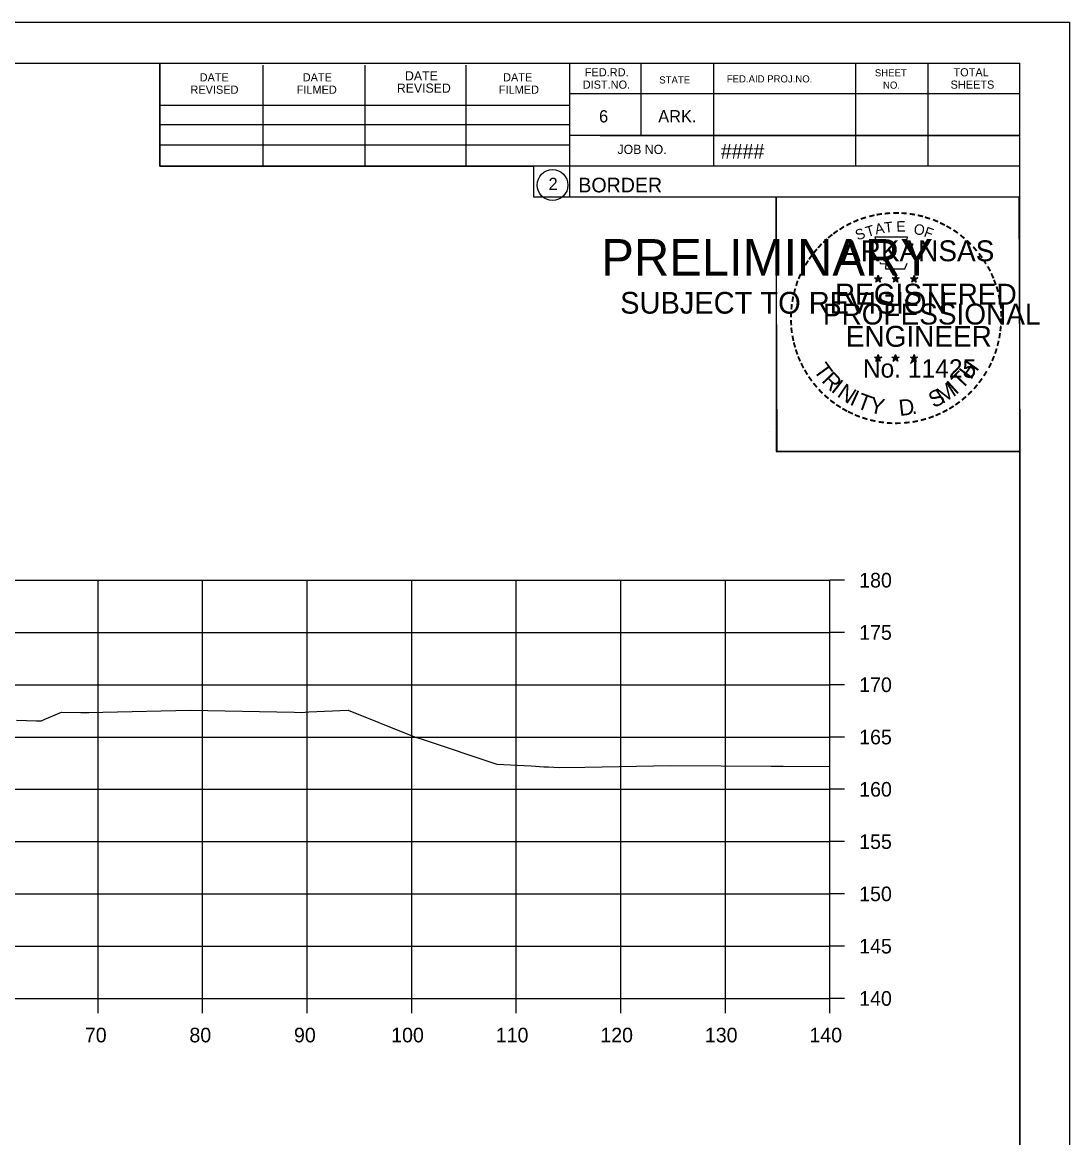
# Model space of a CAD drawing. Extents: x 1368503 to 1373085, y 379840 to 381833.
# Drawn here: x 1372984.8 to 1373085, y 380495 to 380601.6 of the extents above; entities that cross this region are included whole.
import ezdxf

# ---------------------------------------------------------------- set-up
doc = ezdxf.new("R2010")
doc.units = 0
for name, color, linetype in [('S_BRIDGE', 7, 'Continuous'), ('S_EDGE_PAVEMENT', 7, 'Continuous'), ('S_LANDSCAPING', 7, 'Continuous'), ('S_MISC_BOUNDARY', 7, 'Continuous'), ('S_MISC_BOUNDARY_ANNOT', 7, 'Continuous'), ('S_PHOTO_CENTERS', 7, 'Continuous'), ('S_PHOTO_NOTES', 7, 'Continuous'), ('S_TRAILS', 7, 'Continuous')]:
    doc.layers.add(name, color=color, linetype=linetype)

msp = doc.modelspace()

# ---------------------------------------------------------------- linework, layer by layer
at = {"layer": 'S_BRIDGE'}
for p, q in [((1372764.08, 380597.75), (1373080.26, 380597.75)), ((1372998, 380587.87), (1372998, 380597.75)), ((1373007.86, 380587.87), (1373007.86, 380597.55)), ((1373017.62, 380587.87), (1373017.62, 380597.55)), ((1373027.3, 380587.87), (1373027.3, 380597.55)), ((1373037.16, 380597.75), (1373037.16, 380584.95)), ((1373044, 380597.75), (1373044, 380590.81)), ((1373050.94, 380597.75), (1373050.94, 380587.87)), ((1373064.52, 380597.75), (1373064.52, 380587.87)), ((1373071.46, 380597.75), (1373071.46, 380587.87)), ((1373080.26, 380392.29), (1373080.26, 380597.75)), ((1373080.26, 380594.81), (1373037.16, 380594.81)), ((1373080.26, 380594.83), (1373080.26, 380594.83)), ((1372998, 380593.73), (1373037.16, 380593.73)), ((1372998, 380591.87), (1373037.16, 380591.87)), ((1373080.26, 380590.81), (1373037.16, 380590.81)), ((1373040.12, 380590.81), (1373080.26, 380590.81)), ((1372998, 380587.87), (1372998, 380589.93)), ((1372998, 380589.93), (1373037.16, 380589.93)), ((1373080.26, 380587.87), (1372998, 380587.87)), ((1373037.16, 380584.95), (1373080.26, 380584.95))]:
    msp.add_line(p, q, dxfattribs=at)
msp.add_circle((1373035.55, 380586.08), 1.47, dxfattribs=at)
at = {"layer": 'S_EDGE_PAVEMENT'}
for p, q in [((1373062.08, 380508.29), (1373062.08, 380548.29)), ((1373063.48, 380548.29), (1373062.08, 380548.29)), ((1373063.48, 380543.29), (1373062.08, 380543.29)), ((1373063.48, 380538.29), (1373062.08, 380538.29)), ((1373063.48, 380533.29), (1373062.08, 380533.29)), ((1373063.48, 380528.29), (1373062.08, 380528.29)), ((1373063.48, 380523.29), (1373062.08, 380523.29)), ((1373063.48, 380518.29), (1373062.08, 380518.29)), ((1373063.48, 380513.29), (1373062.08, 380513.29)), ((1372782.08, 380508.29), (1373062.08, 380508.29)), ((1372992.08, 380506.89), (1372992.08, 380508.29)), ((1373002.08, 380506.89), (1373002.08, 380508.29)), ((1373012.08, 380506.89), (1373012.08, 380508.29)), ((1373022.08, 380506.89), (1373022.08, 380508.29)), ((1373032.08, 380506.89), (1373032.08, 380508.29)), ((1373042.08, 380506.89), (1373042.08, 380508.29)), ((1373052.08, 380506.89), (1373052.08, 380508.29)), ((1373062.08, 380506.89), (1373062.08, 380508.29)), ((1373063.48, 380508.29), (1373062.08, 380508.29))]:
    msp.add_line(p, q, dxfattribs=at)
at = {"layer": 'S_LANDSCAPING'}
for p, q in [((1373066.7, 380577.46), (1373066.65, 380577.2)), ((1373066.7, 380577.09), (1373066.7, 380577.46)), ((1373066.7, 380577.46), (1373066.74, 380577.21)), ((1373068.37, 380577.46), (1373068.32, 380577.2)), ((1373068.37, 380577.09), (1373068.37, 380577.46)), ((1373068.37, 380577.46), (1373068.41, 380577.21)), ((1373070.13, 380577.44), (1373070.09, 380577.19)), ((1373070.13, 380577.08), (1373070.13, 380577.44)), ((1373070.13, 380577.44), (1373070.18, 380577.19)), ((1373066.35, 380577.2), (1373066.7, 380577.09)), ((1373066.35, 380577.2), (1373066.6, 380577.16)), ((1373066.35, 380577.2), (1373066.58, 380577.08)), ((1373066.48, 380576.79), (1373066.7, 380577.09)), ((1373066.48, 380576.79), (1373066.61, 380577.04)), ((1373066.48, 380576.79), (1373066.69, 380577.01)), ((1373066.91, 380576.79), (1373066.69, 380577.01)), ((1373067.04, 380577.2), (1373066.7, 380577.09)), ((1373066.91, 380576.79), (1373066.7, 380577.09)), ((1373067.04, 380577.2), (1373066.76, 380577.15)), ((1373066.91, 380576.79), (1373066.77, 380577.09)), ((1373067.04, 380577.2), (1373066.84, 380577.1)), ((1373068.02, 380577.2), (1373068.37, 380577.09)), ((1373068.02, 380577.2), (1373068.27, 380577.16)), ((1373068.02, 380577.2), (1373068.25, 380577.08)), ((1373068.15, 380576.79), (1373068.37, 380577.09)), ((1373068.15, 380576.79), (1373068.28, 380577.04)), ((1373068.15, 380576.79), (1373068.36, 380577.01)), ((1373068.58, 380576.79), (1373068.36, 380577.01)), ((1373068.71, 380577.2), (1373068.37, 380577.09)), ((1373068.58, 380576.79), (1373068.37, 380577.09)), ((1373068.71, 380577.2), (1373068.43, 380577.15)), ((1373068.58, 380576.79), (1373068.44, 380577.09)), ((1373068.71, 380577.2), (1373068.51, 380577.1)), ((1373069.78, 380577.19), (1373070.13, 380577.08)), ((1373069.78, 380577.19), (1373070.03, 380577.15)), ((1373069.78, 380577.19), (1373070.02, 380577.07)), ((1373069.91, 380576.78), (1373070.13, 380577.08)), ((1373069.91, 380576.78), (1373070.04, 380577.03)), ((1373069.91, 380576.78), (1373070.13, 380577)), ((1373070.48, 380577.19), (1373070.13, 380577.08)), ((1373070.34, 380576.78), (1373070.13, 380577.08)), ((1373070.34, 380576.78), (1373070.13, 380577)), ((1373070.48, 380577.19), (1373070.19, 380577.14)), ((1373070.34, 380576.78), (1373070.21, 380577.07)), ((1373070.48, 380577.19), (1373070.27, 380577.09)), ((1373066.69, 380569.88), (1373066.65, 380569.63)), ((1373066.69, 380569.52), (1373066.69, 380569.88)), ((1373066.69, 380569.88), (1373066.74, 380569.63)), ((1373068.36, 380569.88), (1373068.32, 380569.63)), ((1373068.36, 380569.52), (1373068.36, 380569.88)), ((1373068.36, 380569.88), (1373068.41, 380569.63)), ((1373070.13, 380569.87), (1373070.09, 380569.62)), ((1373070.13, 380569.51), (1373070.13, 380569.87)), ((1373070.13, 380569.87), (1373070.18, 380569.62)), ((1373066.34, 380569.63), (1373066.69, 380569.52)), ((1373066.34, 380569.63), (1373066.6, 380569.58)), ((1373066.34, 380569.63), (1373066.58, 380569.51)), ((1373066.48, 380569.22), (1373066.69, 380569.52)), ((1373066.48, 380569.22), (1373066.6, 380569.47)), ((1373066.48, 380569.22), (1373066.69, 380569.44)), ((1373067.04, 380569.63), (1373066.69, 380569.52)), ((1373066.9, 380569.22), (1373066.69, 380569.52)), ((1373066.9, 380569.22), (1373066.69, 380569.44)), ((1373067.04, 380569.63), (1373066.75, 380569.58)), ((1373066.9, 380569.22), (1373066.77, 380569.51)), ((1373067.04, 380569.63), (1373066.83, 380569.53)), ((1373068.01, 380569.63), (1373068.36, 380569.52)), ((1373068.01, 380569.63), (1373068.26, 380569.58)), ((1373068.01, 380569.63), (1373068.25, 380569.51)), ((1373068.14, 380569.22), (1373068.36, 380569.52)), ((1373068.14, 380569.22), (1373068.27, 380569.47)), ((1373068.14, 380569.22), (1373068.36, 380569.44)), ((1373068.71, 380569.63), (1373068.36, 380569.52)), ((1373068.57, 380569.22), (1373068.36, 380569.52)), ((1373068.57, 380569.22), (1373068.36, 380569.44)), ((1373068.71, 380569.63), (1373068.42, 380569.58)), ((1373068.57, 380569.22), (1373068.44, 380569.51)), ((1373068.71, 380569.63), (1373068.5, 380569.53)), ((1373069.78, 380569.62), (1373070.13, 380569.51)), ((1373069.78, 380569.62), (1373070.03, 380569.57)), ((1373069.78, 380569.62), (1373070.02, 380569.5)), ((1373069.91, 380569.21), (1373070.13, 380569.51)), ((1373069.91, 380569.21), (1373070.04, 380569.46)), ((1373069.91, 380569.21), (1373070.13, 380569.43)), ((1373070.47, 380569.62), (1373070.13, 380569.51)), ((1373070.34, 380569.21), (1373070.13, 380569.51)), ((1373070.34, 380569.21), (1373070.13, 380569.43)), ((1373070.47, 380569.62), (1373070.19, 380569.57)), ((1373070.34, 380569.21), (1373070.2, 380569.5)), ((1373070.47, 380569.62), (1373070.27, 380569.52))]:
    msp.add_line(p, q, dxfattribs=at)
for points in [[(1373066.39, 380581.08), (1373066.66, 380580.25)], [(1373069.9, 380580.16), (1373070.04, 380580.44), (1373069.36, 380580.42), (1373069.5, 380581.08), (1373066.39, 380581.08)], [(1373066.88, 380578.66), (1373066.88, 380578.57), (1373067.44, 380578.55), (1373067.39, 380578.08), (1373069.26, 380578.08), (1373069.46, 380578.61)], [(1373066.7, 380577.46), (1373066.91, 380576.79), (1373066.35, 380577.2), (1373067.04, 380577.2), (1373066.48, 380576.79), (1373066.7, 380577.46)], [(1373068.37, 380577.46), (1373068.58, 380576.79), (1373068.02, 380577.2), (1373068.71, 380577.2), (1373068.15, 380576.79), (1373068.37, 380577.46)], [(1373070.13, 380577.44), (1373070.34, 380576.78), (1373069.78, 380577.19), (1373070.48, 380577.19), (1373069.91, 380576.78), (1373070.13, 380577.44)], [(1373066.69, 380569.88), (1373066.9, 380569.22), (1373066.34, 380569.63), (1373067.04, 380569.63), (1373066.48, 380569.22), (1373066.69, 380569.88)], [(1373068.36, 380569.88), (1373068.57, 380569.22), (1373068.01, 380569.63), (1373068.71, 380569.63), (1373068.14, 380569.22), (1373068.36, 380569.88)], [(1373070.13, 380569.87), (1373070.34, 380569.21), (1373069.78, 380569.62), (1373070.47, 380569.62), (1373069.91, 380569.21), (1373070.13, 380569.87)]]:
    msp.add_lwpolyline(points, dxfattribs=at)
for centre, radius in [((1373066.69, 380577.09), 0.172), ((1373066.69, 380577.09), 0.145), ((1373068.36, 380577.09), 0.172), ((1373068.36, 380577.09), 0.145), ((1373070.13, 380577.08), 0.172), ((1373070.13, 380577.08), 0.145), ((1373066.69, 380577.09), 0.116), ((1373066.69, 380577.09), 0.0991), ((1373066.69, 380577.09), 0.0747), ((1373066.69, 380577.09), 0.0495), ((1373066.69, 380577.09), 0.0296), ((1373068.36, 380577.09), 0.116), ((1373068.36, 380577.09), 0.0991), ((1373068.36, 380577.09), 0.0747), ((1373068.36, 380577.09), 0.0495), ((1373068.36, 380577.09), 0.0296), ((1373070.13, 380577.08), 0.116), ((1373070.13, 380577.08), 0.0991), ((1373070.13, 380577.08), 0.0747), ((1373070.13, 380577.08), 0.0495), ((1373070.13, 380577.08), 0.0296), ((1373066.69, 380569.52), 0.172), ((1373066.69, 380569.52), 0.145), ((1373066.69, 380569.52), 0.116), ((1373066.69, 380569.52), 0.0991), ((1373066.69, 380569.52), 0.0747), ((1373066.69, 380569.52), 0.0495), ((1373066.69, 380569.52), 0.0296), ((1373068.36, 380569.52), 0.172), ((1373068.36, 380569.52), 0.145), ((1373068.36, 380569.52), 0.116), ((1373068.36, 380569.52), 0.0991), ((1373068.36, 380569.52), 0.0747), ((1373068.36, 380569.52), 0.0495), ((1373068.36, 380569.52), 0.0296), ((1373070.13, 380569.51), 0.172), ((1373070.13, 380569.51), 0.145), ((1373070.13, 380569.51), 0.116), ((1373070.13, 380569.51), 0.0991), ((1373070.13, 380569.51), 0.0747), ((1373070.13, 380569.51), 0.0495), ((1373070.13, 380569.51), 0.0296)]:
    msp.add_circle(centre, radius, dxfattribs=at)
at = {"layer": 'S_MISC_BOUNDARY'}
msp.add_lwpolyline([(1372984.28, 380534.9), (1372986.19, 380534.85), (1372986.67, 380534.84), (1372986.92, 380534.96), (1372988.59, 380535.67), (1372990.45, 380535.65), (1372991.2, 380535.65), (1372992.53, 380535.67), (1373000.92, 380535.85), (1373010.85, 380535.66), (1373011.53, 380535.65), (1373012.24, 380535.69), (1373015.99, 380535.87), (1373022.02, 380533.44), (1373022.44, 380533.28), (1373023.07, 380533.08), (1373030.21, 380530.71), (1373033.5, 380530.52), (1373034.72, 380530.45), (1373035.17, 380530.43), (1373036.17, 380530.39), (1373038.64, 380530.41), (1373046.87, 380530.56), (1373056.46, 380530.49), (1373056.89, 380530.49), (1373057.62, 380530.49), (1373062.08, 380530.48)], dxfattribs=at)
at = {"layer": 'S_PHOTO_CENTERS'}
for p, q in [((1372782.08, 380548.29), (1373062.08, 380548.29)), ((1372992.08, 380508.29), (1372992.08, 380548.29)), ((1373002.08, 380508.29), (1373002.08, 380548.29)), ((1373012.08, 380508.29), (1373012.08, 380548.29)), ((1373022.08, 380508.29), (1373022.08, 380548.29)), ((1373032.08, 380508.29), (1373032.08, 380548.29)), ((1373042.08, 380508.29), (1373042.08, 380548.29)), ((1373052.08, 380508.29), (1373052.08, 380548.29)), ((1373062.08, 380508.29), (1373062.08, 380548.29)), ((1372782.08, 380543.29), (1373062.08, 380543.29)), ((1372782.08, 380538.29), (1373062.08, 380538.29)), ((1372782.08, 380533.29), (1373062.08, 380533.29)), ((1372782.08, 380528.29), (1373062.08, 380528.29)), ((1372782.08, 380523.29), (1373062.08, 380523.29)), ((1372782.08, 380518.29), (1373062.08, 380518.29)), ((1372782.08, 380513.29), (1373062.08, 380513.29)), ((1372782.08, 380508.29), (1373062.08, 380508.29))]:
    msp.add_line(p, q, dxfattribs=at)
at = {"layer": 'S_PHOTO_NOTES'}
for p, q in [((1372751.68, 380601.64), (1373085.01, 380601.64)), ((1373056.3, 380562.49), (1373056.3, 380562.49))]:
    msp.add_line(p, q, dxfattribs=at)
for points in [[(1372751.67, 380601.64), (1373085.01, 380601.64), (1373085.01, 380388.3), (1372751.67, 380388.3)], [(1372998, 380597.75), (1372998, 380587.87), (1373033.73, 380587.87), (1373033.73, 380584.95), (1373056.93, 380584.95), (1373056.93, 380560.61), (1373080.26, 380560.61), (1373080.26, 380392.29), (1372764.08, 380392.29), (1372764.08, 380597.75)], [(1373056.93, 380584.95), (1373080.14, 380584.95), (1373080.26, 380560.61), (1373057.05, 380560.61)]]:
    msp.add_lwpolyline(points, close=True, dxfattribs=at)

# ---------------------------------------------------------------- texts
at = {"layer": 'S_BRIDGE'}
for s, height, p in [('DATE', 0.782, (1373001.8, 380595.99)), ('DATE', 0.782, (1373011.66, 380595.99)), ('DATE', 0.879, (1373021.44, 380596.09)), ('DATE', 0.782, (1373030.82, 380595.99)), ('FED.RD.', 0.782, (1373038.64, 380596.47)), ('STATE', 0.684, (1373045.76, 380595.79)), ('FED.AID PROJ.NO.', 0.684, (1373052.22, 380595.89)), ('SHEET', 0.684, (1373066.38, 380596.47)), ('TOTAL', 0.782, (1373073.9, 380596.47)), ('REVISED', 0.782, (1373000.92, 380594.81)), ('FILMED', 0.782, (1373011.08, 380594.81)), ('REVISED', 0.879, (1373020.66, 380594.91)), ('FILMED', 0.782, (1373030.42, 380594.81)), ('DIST.NO.', 0.782, (1373038.44, 380595.29)), ('NO.', 0.684, (1373067.16, 380595.29)), ('SHEETS', 0.782, (1373073.62, 380595.29)), ('6', 1.17, (1373040, 380592.07)), ('ARK.', 1.172, (1373045.66, 380592.07)), ('JOB NO.', 0.879, (1373041.76, 380589.05)), ('####', 1.4, (1373051.64, 380588.61)), ('2', 1.17, (1373035.17, 380585.6)), ('BORDER', 1.4, (1373038.02, 380585.38))]:
    msp.add_text(s, height=height, rotation=360, dxfattribs=at).set_placement(p)
at = {"layer": 'S_LANDSCAPING'}
for s, height, rotation, p in [('-', 1.6, 24.3072, (1373064.5, 380581.94)), ('-', 1.6, 19.1761, (1373065.14, 380582.21)), ('-', 1.6, 13.6301, (1373065.89, 380582.45)), ('-', 1.6, 10.2193, (1373066.56, 380582.61)), ('T', 1, 6.0228, (1373067.33, 380581.51)), ('-', 1.6, 5.8968, (1373067.29, 380582.72)), ('-', 1.6, 0.1862, (1373068.06, 380582.79)), ('E', 1, 0.8323, (1373068.44, 380581.62)), ('-', 1.6, 357.743, (1373068.79, 380582.78)), ('-', 1.6, 352.1617, (1373069.53, 380582.72)), ('-', 1.6, 347.2049, (1373070.25, 380582.61)), ('-', 1.6, 342.3362, (1373070.89, 380582.45)), ('-', 1.6, 337.8551, (1373071.62, 380582.23)), ('-', 1.6, 334.1211, (1373072.25, 380581.96)), ('-', 1.6, 36.2317, (1373062.69, 380580.86)), ('-', 1.6, 34.0636, (1373063.27, 380581.25)), ('-', 1.6, 28.7918, (1373063.87, 380581.62)), ('S', 1, 21.594, (1373064.74, 380580.76)), ('T', 1, 16.4036, (1373065.66, 380581.09)), ('A', 1, 11.2132, (1373066.48, 380581.34)), ('O', 1, 350.4515, (1373070.04, 380581.41)), ('F', 1, 340.0707, (1373070.99, 380581.18)), ('-', 1.6, 329.6409, (1373072.83, 380581.68)), ('-', 1.6, 325.8627, (1373073.47, 380581.32)), ('-', 1.6, 48.423, (1373061.34, 380579.58)), ('-', 1.6, 42.9622, (1373061.78, 380580.06)), ('-', 1.6, 38.9507, (1373062.22, 380580.48)), ('ARKANSAS', 2, 360, (1373063.24, 380578.79)), ('-', 1.6, 320.5297, (1373074.08, 380580.89)), ('-', 1.6, 315.5786, (1373074.68, 380580.4)), ('-', 1.6, 54.2325, (1373060.52, 380578.53)), ('-', 1.6, 50.6142, (1373060.93, 380579.1)), ('-', 1.6, 309.8797, (1373075.25, 380579.85)), ('-', 1.6, 306.6522, (1373075.78, 380579.25)), ('-', 1.6, 58.0706, (1373060.2, 380578)), ('-', 1.4, 303.6753, (1373076.26, 380578.68)), ('-', 1.6, 299.6684, (1373076.58, 380578.08)), ('-', 1.6, 67.7743, (1373059.62, 380576.78)), ('-', 1.6, 62.8713, (1373059.88, 380577.39)), ('-', 1.6, 294.6628, (1373076.91, 380577.46)), ('-', 1.6, 75.461, (1373059.21, 380575.43)), ('-', 1.6, 72.3945, (1373059.4, 380576.15)), ('REGISTERED', 2, 360, (1373062.56, 380574.64)), ('DWB', 0.01, 360, (1373066.68, 380577.09)), ('DWB', 0.01, 360, (1373068.35, 380577.09)), ('DWB', 0.01, 360, (1373070.12, 380577.08)), ('-', 1.6, 290.5728, (1373077.16, 380576.89)), ('-', 1.6, 285.1233, (1373077.4, 380576.31)), ('-', 1.6, 81.2013, (1373059.08, 380574.72)), ('-', 1.6, 280.5493, (1373077.6, 380575.56)), ('-', 1.6, 85.1863, (1373059, 380574.03)), ('PROFESSIONAL', 2, 360, (1373061.41, 380572.74)), ('-', 1.6, 276.5962, (1373077.76, 380574.8)), ('-', 1.6, 274.3301, (1373077.82, 380574.07)), ('-', 1.6, 94.1959, (1373059.01, 380572.6)), ('-', 1.6, 89.0622, (1373058.97, 380573.33)), ('-', 1.6, 269.9407, (1373077.85, 380573.44)), ('-', 1.6, 98.9479, (1373059.08, 380571.94)), ('ENGINEER', 2, 360, (1373063.6, 380570.61)), ('-', 1.6, 260.9953, (1373077.76, 380572.12)), ('-', 1.6, 263.5172, (1373077.83, 380572.78)), ('-', 1.6, 101.7149, (1373059.22, 380571.2)), ('-', 1.6, 105.4578, (1373059.38, 380570.61)), ('-', 1.6, 255.7626, (1373077.65, 380571.44)), ('-', 1.6, 109.0874, (1373059.59, 380569.98)), ('-', 1.6, 247.8887, (1373077.25, 380570.05)), ('-', 1.6, 252.8681, (1373077.47, 380570.72)), ('-', 1.6, 114.0643, (1373059.85, 380569.38)), ('-', 1.6, 115.7289, (1373060.15, 380568.76)), ('T', 1.54, 306.0406, (1373060.45, 380568.36)), ('No. 11425', 1.757, 360, (1373065.23, 380567.66)), ('DWB', 0.01, 360, (1373066.68, 380569.51)), ('DWB', 0.01, 360, (1373068.35, 380569.51)), ('DWB', 0.01, 360, (1373070.11, 380569.5)), ('H', 1.54, 54.6088, (1373075.57, 380567.39)), ('-', 1.6, 244.6197, (1373076.99, 380569.42)), ('-', 1.6, 120.4471, (1373060.51, 380568.18)), ('-', 1.6, 125.8934, (1373060.91, 380567.62)), ('R', 1.54, 314.005, (1373061.21, 380567.31)), ('T', 1.54, 46.6444, (1373074.68, 380566.45)), ('-', 1.6, 233.8452, (1373076.19, 380568.02)), ('-', 1.6, 239.0712, (1373076.59, 380568.67)), ('-', 1.6, 130.7181, (1373061.37, 380567.07)), ('-', 1.6, 134.2238, (1373061.89, 380566.52)), ('I', 1.54, 321.9694, (1373062.11, 380566.38)), ('N', 1.54, 326.5002, (1373062.68, 380565.91)), ('M', 1.54, 32.6563, (1373072.84, 380565.12)), ('I', 1.54, 42.1136, (1373074.12, 380565.97)), ('-', 1.6, 231.2538, (1373075.76, 380567.45)), ('-', 1.6, 138.9338, (1373062.42, 380566.06)), ('-', 1.6, 144.6463, (1373062.97, 380565.65)), ('I', 1.54, 335.3603, (1373063.89, 380565.12)), ('T', 1.54, 339.8912, (1373064.55, 380564.79)), ('Y', 1.54, 347.8556, (1373065.77, 380564.35)), ('D', 1.54, 6.3969, (1373068.75, 380563.99)), ('S', 1.54, 26.9312, (1373072, 380564.72)), ('-', 1.6, 221.0851, (1373074.76, 380566.38)), ('-', 1.6, 225.7653, (1373075.28, 380566.89)), ('-', 1.6, 148.0898, (1373063.53, 380565.28)), ('-', 1.6, 151.5704, (1373064.11, 380564.95)), ('-', 1.6, 154.6002, (1373064.63, 380564.71)), ('.', 1.54, 13.7642, (1373069.94, 380564.12)), ('-', 1.6, 207.3568, (1373073.12, 380565.17)), ('-', 1.6, 212.2491, (1373073.68, 380565.52)), ('-', 1.6, 215.7363, (1373074.21, 380565.91)), ('-', 1.6, 158.5612, (1373065.26, 380564.45)), ('-', 1.6, 162.7983, (1373065.95, 380564.24)), ('-', 1.6, 167.5555, (1373066.66, 380564.08)), ('-', 1.6, 173.1155, (1373067.43, 380563.97)), ('-', 1.6, 176.5183, (1373068.18, 380563.91)), ('-', 1.6, 181.5918, (1373068.92, 380563.93)), ('-', 1.6, 185.8167, (1373069.73, 380564.01)), ('-', 1.6, 191.2858, (1373070.47, 380564.14)), ('-', 1.6, 195.4743, (1373071.2, 380564.34)), ('-', 1.6, 200.7184, (1373071.88, 380564.58)), ('-', 1.6, 204.2516, (1373072.49, 380564.85))]:
    msp.add_text(s, height=height, rotation=rotation, dxfattribs=at).set_placement(p)
at = {"layer": 'S_MISC_BOUNDARY_ANNOT'}
for s, height, p in [('PRELIMINARY', 3.5, (1373040.21, 380577.41)), ('DWB', 0.01, (1373040.96, 380579.26)), ('SUBJECT TO REVISION', 2.0751, (1373042.02, 380573.78))]:
    msp.add_text(s, height=height, rotation=360, dxfattribs=at).set_placement(p)
at = {"layer": 'S_TRAILS'}
for s, p in [('180', (1373064.88, 380547.59)), ('175', (1373064.88, 380542.59)), ('170', (1373064.88, 380537.59)), ('165', (1373064.88, 380532.59)), ('160', (1373064.88, 380527.59)), ('155', (1373064.88, 380522.59)), ('150', (1373064.88, 380517.59)), ('145', (1373064.88, 380512.59)), ('140', (1373064.88, 380507.59)), ('70', (1372990.82, 380504.09)), ('80', (1373000.82, 380504.09)), ('90', (1373010.82, 380504.09)), ('100', (1373020.12, 380504.09)), ('110', (1373030.12, 380504.09)), ('120', (1373040.12, 380504.09)), ('130', (1373050.12, 380504.09)), ('140', (1373060.12, 380504.09))]:
    msp.add_text(s, height=1.4, dxfattribs=at).set_placement(p)

doc.saveas('drawing.dxf')
